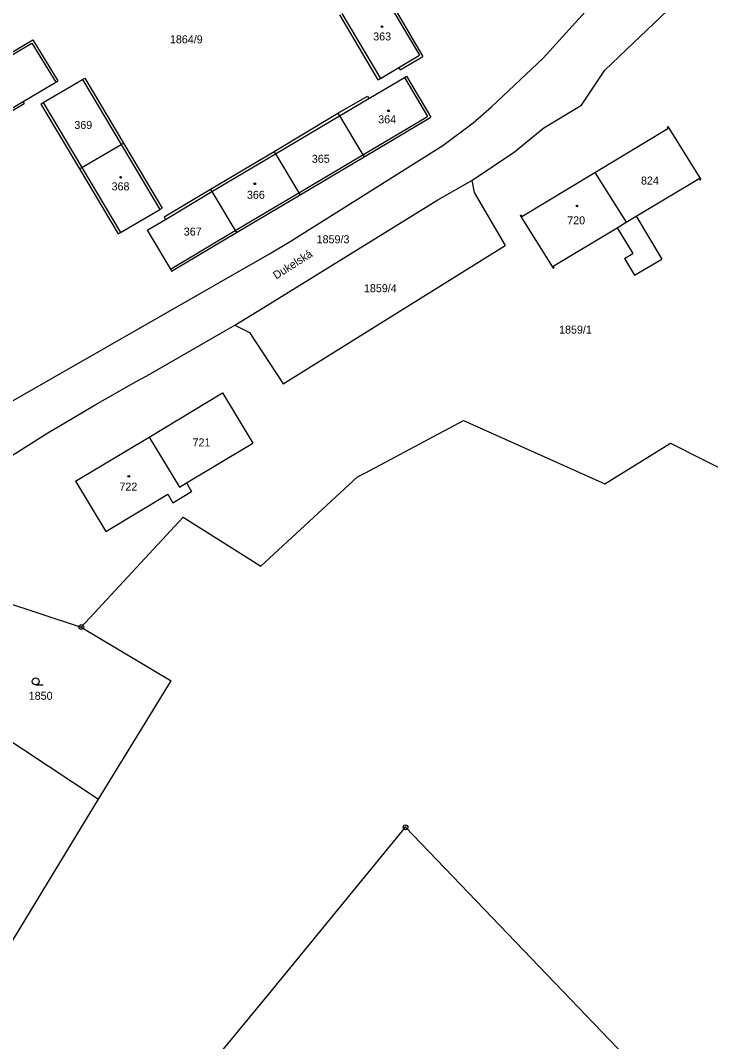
# Model space of a CAD drawing. Extents: x -763205 to -760228, y -1155311 to -1152844.
# Drawn here: x -761916.2 to -761769.7, y -1154992.1 to -1154775.3 of the extents above; entities that cross this region are included whole.
import ezdxf

# ---------------------------------------------------------------- set-up
doc = ezdxf.new("R2010")
doc.units = 0
for name, color, linetype in [('Vrstva 1', 7, 'Continuous'), ('Vrstva 15', 7, 'Continuous'), ('Vrstva 18', 7, 'Continuous'), ('Vrstva 19', 7, 'Continuous'), ('Vrstva 24', 7, 'Continuous'), ('Vrstva 25', 7, 'Continuous'), ('Vrstva 4', 7, 'Continuous')]:
    doc.layers.add(name, color=color, linetype=linetype)

msp = doc.modelspace()

# ---------------------------------------------------------------- linework, layer by layer
at = {"layer": 'Vrstva 1'}
for p, q in [((-761805.24, -1154783.27), (-761785.67, -1154761.54)), ((-761787.57, -1154781.41), (-761770.49, -1154765.16)), ((-761839.19, -1154768.57), (-761830.79, -1154782.91)), ((-761848.52, -1154774.11), (-761840.34, -1154787.91)), ((-761927.77, -1154787.79), (-761913.61, -1154779.42)), ((-761913.61, -1154779.42), (-761908.27, -1154788.11)), ((-761835.6, -1154785.78), (-761830.79, -1154782.91)), ((-761792.2, -1154785.82), (-761787.57, -1154781.41)), ((-761839.82, -1154787.6), (-761835.91, -1154785.26)), ((-761835.91, -1154785.26), (-761835.6, -1154785.78)), ((-761816.22, -1154793.59), (-761805.24, -1154783.27)), ((-761842.28, -1154791.86), (-761834.68, -1154787.35)), ((-761834.68, -1154787.35), (-761834.25, -1154787.1)), ((-761834.25, -1154787.1), (-761829.1, -1154795.81)), ((-761797.12, -1154793.29), (-761792.2, -1154785.82)), ((-761915.68, -1154792.48), (-761908.7, -1154788.36)), ((-761911.4, -1154792.72), (-761903.06, -1154787.83)), ((-761908.7, -1154788.36), (-761908.27, -1154788.11)), ((-761903.06, -1154787.83), (-761902.53, -1154787.54)), ((-761902.53, -1154787.54), (-761894.34, -1154801.32)), ((-761840.34, -1154787.91), (-761839.82, -1154787.6)), ((-761848.83, -1154794.99), (-761842.59, -1154791.34)), ((-761842.59, -1154791.34), (-761842.28, -1154791.86)), ((-761922.23, -1154796.94), (-761915.42, -1154792.91)), ((-761915.68, -1154792.48), (-761915.42, -1154792.91)), ((-761911.92, -1154793.03), (-761911.4, -1154792.72)), ((-761911.92, -1154793.03), (-761903.71, -1154806.81)), ((-761820.16, -1154797), (-761816.22, -1154793.59)), ((-761805.16, -1154798.09), (-761797.12, -1154793.29)), ((-761862.39, -1154803.1), (-761848.83, -1154794.99)), ((-761848.83, -1154794.99), (-761848.5, -1154795.55)), ((-761848.5, -1154795.55), (-761843.55, -1154803.81)), ((-761843.29, -1154804.24), (-761829.1, -1154795.81)), ((-761826.57, -1154801.81), (-761820.16, -1154797)), ((-761811.35, -1154803.2), (-761805.16, -1154798.09)), ((-761794.27, -1154807.56), (-761778.78, -1154798.23)), ((-761778.97, -1154797.92), (-761778.81, -1154797.82)), ((-761778.97, -1154797.92), (-761778.78, -1154798.23)), ((-761778.81, -1154797.82), (-761771.81, -1154809.05)), ((-761903.2, -1154806.5), (-761894.86, -1154801.63)), ((-761894.86, -1154801.63), (-761894.34, -1154801.32)), ((-761894.34, -1154801.32), (-761886.14, -1154815.11)), ((-761859, -1154822.2), (-761826.57, -1154801.81)), ((-761875.89, -1154811.12), (-761862.39, -1154803.1)), ((-761862.39, -1154803.1), (-761862.08, -1154803.62)), ((-761862.08, -1154803.62), (-761857.14, -1154811.88)), ((-761856.88, -1154812.31), (-761843.29, -1154804.24)), ((-761843.55, -1154803.81), (-761843.29, -1154804.24)), ((-761820.38, -1154809.26), (-761811.35, -1154803.2)), ((-761903.71, -1154806.81), (-761903.2, -1154806.5)), ((-761903.71, -1154806.81), (-761895.52, -1154820.58)), ((-761809.78, -1154816.88), (-761794.27, -1154807.56)), ((-761794.27, -1154807.56), (-761787.67, -1154818.14)), ((-761785.52, -1154816.85), (-761772.16, -1154808.83)), ((-761772.16, -1154808.83), (-761771.98, -1154809.15)), ((-761771.98, -1154809.15), (-761771.81, -1154809.05)), ((-761885.72, -1154816.99), (-761875.89, -1154811.12)), ((-761875.89, -1154811.12), (-761875.58, -1154811.63)), ((-761827.64, -1154813.38), (-761820.38, -1154809.26)), ((-761820.38, -1154809.26), (-761819.91, -1154811.79)), ((-761875.58, -1154811.63), (-761870.64, -1154819.9)), ((-761870.39, -1154820.33), (-761856.88, -1154812.31)), ((-761864.74, -1154836.33), (-761827.64, -1154813.38)), ((-761857.14, -1154811.88), (-761856.88, -1154812.31)), ((-761819.91, -1154811.79), (-761813.36, -1154823.09)), ((-761895, -1154820.27), (-761886.66, -1154815.42)), ((-761886.66, -1154815.42), (-761886.14, -1154815.11)), ((-761889.34, -1154819.8), (-761885.42, -1154817.51)), ((-761885.72, -1154816.99), (-761885.42, -1154817.51)), ((-761810.14, -1154816.67), (-761809.97, -1154816.57)), ((-761810.14, -1154816.67), (-761803.17, -1154827.88)), ((-761809.97, -1154816.57), (-761809.78, -1154816.88)), ((-761787.67, -1154818.14), (-761785.52, -1154816.85)), ((-761785.52, -1154816.85), (-761780.06, -1154825.94)), ((-761889.34, -1154819.8), (-761884.38, -1154828.09)), ((-761870.64, -1154819.9), (-761870.39, -1154820.33)), ((-761803.18, -1154827.46), (-761789.56, -1154819.28)), ((-761789.56, -1154819.28), (-761786.26, -1154824.78)), ((-761895.52, -1154820.58), (-761895, -1154820.27)), ((-761884.15, -1154828.5), (-761870.39, -1154820.33)), ((-761863.34, -1154824.84), (-761859, -1154822.2)), ((-761860.45, -1154852.46), (-761813.36, -1154823.09)), ((-761940.62, -1154868.99), (-761863.34, -1154824.84)), ((-761787.97, -1154825.81), (-761786.26, -1154824.78)), ((-761787.97, -1154825.81), (-761785.85, -1154829.34)), ((-761785.85, -1154829.34), (-761780.06, -1154825.94)), ((-761884.38, -1154828.09), (-761884.15, -1154828.5)), ((-761803.18, -1154827.46), (-761802.99, -1154827.78)), ((-761803.17, -1154827.88), (-761802.99, -1154827.78)), ((-761870.71, -1154839.99), (-761864.74, -1154836.33)), ((-761884.7, -1154848.02), (-761870.71, -1154839.99)), ((-761870.71, -1154839.99), (-761867.63, -1154841.55)), ((-761867.63, -1154841.55), (-761860.45, -1154852.46)), ((-761889.42, -1154850.72), (-761884.7, -1154848.02)), ((-761898.25, -1154855.7), (-761891.65, -1154851.96)), ((-761891.65, -1154851.96), (-761889.42, -1154850.72)), ((-761888.88, -1154863.74), (-761873.31, -1154854.39)), ((-761873.31, -1154854.39), (-761866.9, -1154865.04)), ((-761900.4, -1154856.91), (-761898.25, -1154855.7)), ((-761905.27, -1154859.78), (-761900.4, -1154856.91)), ((-761910.43, -1154862.84), (-761905.27, -1154859.78)), ((-761843.01, -1154871.33), (-761822.19, -1154860.24)), ((-761822.19, -1154860.24), (-761792.17, -1154873.69)), ((-761918.16, -1154867.76), (-761910.43, -1154862.84)), ((-761904.52, -1154873.14), (-761888.88, -1154863.74)), ((-761888.88, -1154863.74), (-761882.49, -1154874.37)), ((-761881, -1154873.5), (-761866.9, -1154865.04)), ((-761792.17, -1154873.69), (-761778.23, -1154865.02)), ((-761778.23, -1154865.02), (-761736.83, -1154886.18)), ((-761844.66, -1154872.21), (-761843.01, -1154871.33)), ((-761904.52, -1154873.14), (-761898.14, -1154883.79)), ((-761882.49, -1154874.37), (-761881, -1154873.5)), ((-761881, -1154873.5), (-761879.93, -1154875.3)), ((-761865.17, -1154891.18), (-761844.66, -1154872.21)), ((-761898.14, -1154883.79), (-761884.98, -1154875.86)), ((-761884.98, -1154875.86), (-761883.85, -1154877.75)), ((-761883.85, -1154877.75), (-761879.93, -1154875.3)), ((-761903.31, -1154904.09), (-761881.72, -1154880.79)), ((-761881.72, -1154880.79), (-761867.53, -1154889.7)), ((-761867.53, -1154889.7), (-761865.17, -1154891.18)), ((-761920.24, -1154898.55), (-761903.31, -1154904.09)), ((-761903.31, -1154904.09), (-761884.24, -1154915.53)), ((-761899.65, -1154940.66), (-761884.24, -1154915.53)), ((-761922.9, -1154925.32), (-761899.65, -1154940.66)), ((-761929.86, -1154990.35), (-761899.65, -1154940.66)), ((-761863.88, -1154982.47), (-761834.48, -1154946.63)), ((-761834.48, -1154946.63), (-761760.92, -1155023.22)), ((-761874.54, -1154995.48), (-761863.88, -1154982.47))]:
    msp.add_line(p, q, dxfattribs=at)
at = {"layer": 'Vrstva 24'}
for centre, radius in [((-761903.31, -1154904.09), 0.5), ((-761903.31, -1154904.09), 0.1), ((-761834.48, -1154946.63), 0.5), ((-761834.48, -1154946.63), 0.1)]:
    msp.add_circle(centre, radius, dxfattribs=at)
at = {"layer": 'Vrstva 25'}
msp.add_line((-761913, -1154916.39), (-761911.4, -1154916.39), dxfattribs=at)
for centre, radius in [((-761839.48, -1154776.59), 0.175), ((-761838.12, -1154794.45), 0.175), ((-761894.97, -1154808.58), 0.175), ((-761866.48, -1154809.95), 0.175), ((-761798.1, -1154814.67), 0.175), ((-761893.23, -1154872.09), 0.175), ((-761913, -1154915.64), 0.75)]:
    msp.add_circle(centre, radius, dxfattribs=at)
at = {"layer": 'Vrstva 4'}
for p, q in [((-761839.7, -1154768.88), (-761831.53, -1154782.65)), ((-761848.01, -1154773.81), (-761839.82, -1154787.6)), ((-761927.52, -1154788.22), (-761913.79, -1154780.1)), ((-761913.79, -1154780.1), (-761908.7, -1154788.36)), ((-761835.91, -1154785.26), (-761831.53, -1154782.65)), ((-761834.68, -1154787.35), (-761829.79, -1154795.64)), ((-761903.06, -1154787.83), (-761894.86, -1154801.63)), ((-761922.48, -1154796.51), (-761915.68, -1154792.48)), ((-761911.4, -1154792.72), (-761903.2, -1154806.5)), ((-761848.5, -1154795.55), (-761842.28, -1154791.86)), ((-761862.08, -1154803.62), (-761848.5, -1154795.55)), ((-761843.55, -1154803.81), (-761829.79, -1154795.64)), ((-761894.86, -1154801.63), (-761886.66, -1154815.42)), ((-761875.58, -1154811.63), (-761862.08, -1154803.62)), ((-761857.14, -1154811.88), (-761843.55, -1154803.81)), ((-761903.2, -1154806.5), (-761895, -1154820.27)), ((-761885.42, -1154817.51), (-761875.58, -1154811.63)), ((-761870.64, -1154819.9), (-761857.14, -1154811.88)), ((-761884.38, -1154828.09), (-761870.64, -1154819.9)), ((-761789.56, -1154819.28), (-761787.67, -1154818.14))]:
    msp.add_line(p, q, dxfattribs=at)

# ---------------------------------------------------------------- texts
at = {"layer": 'Vrstva 15'}
msp.add_text('Dukelská', height=1.7, rotation=32.544, dxfattribs=at).set_placement((-761861.939, -1154830.308))
at = {"layer": 'Vrstva 18'}
for s, p in [('1864/9', (-761884.497, -1154780.13)), ('1859/3', (-761853.357, -1154822.59)), ('1859/4', (-761843.317, -1154832.99)), ('1859/1', (-761801.887, -1154841.78)), ('1850', (-761914.467, -1154919.55))]:
    msp.add_text(s, height=1.7, dxfattribs=at).set_placement(p)
at = {"layer": 'Vrstva 19'}
for s, p in [('363', (-761841.353, -1154779.51)), ('364', (-761840.283, -1154797.12)), ('369', (-761904.793, -1154798.31)), ('365', (-761854.373, -1154805.5)), ('824', (-761784.503, -1154810.12)), ('368', (-761896.883, -1154811.36)), ('366', (-761868.153, -1154813.14)), ('720', (-761800.163, -1154818.57)), ('367', (-761881.563, -1154820.96)), ('721', (-761879.693, -1154865.73)), ('722', (-761895.223, -1154875.12))]:
    msp.add_text(s, height=1.7, dxfattribs=at).set_placement(p)

doc.saveas('drawing.dxf')
